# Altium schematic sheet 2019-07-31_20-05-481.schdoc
size 518 x 147 mm; SheetNumber: 1; SheetTotal: 1
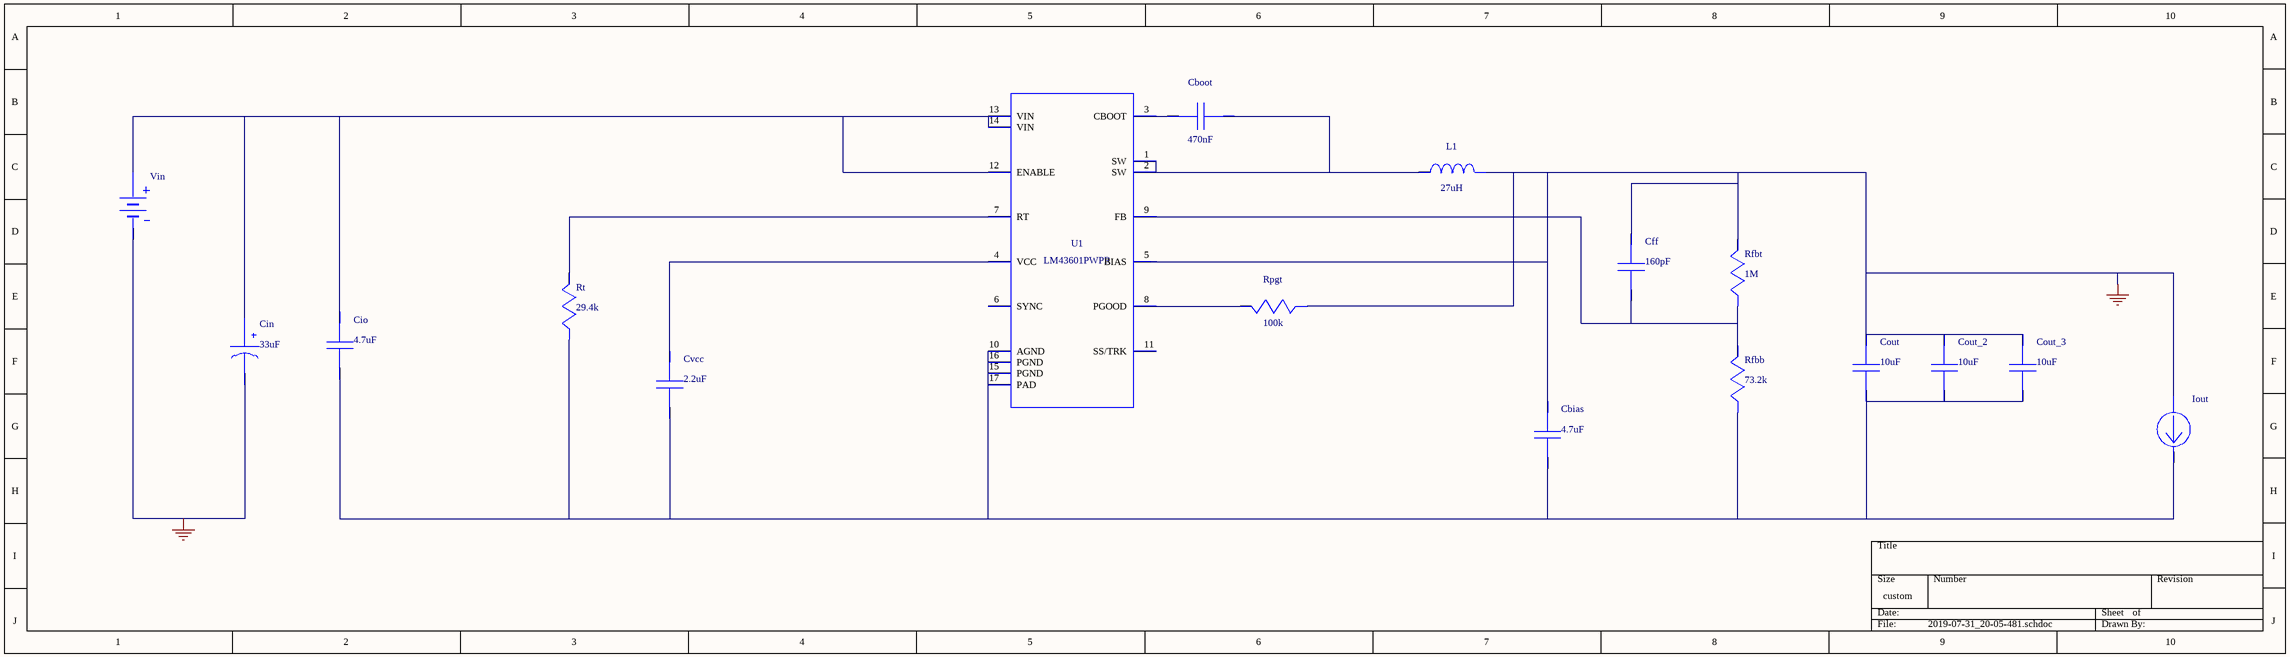
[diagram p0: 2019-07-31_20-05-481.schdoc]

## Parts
Cbias  value 4.7uF  (hidden comment: TMK212BJ475KG-T)
Cboot  value 470nF  (hidden comment: GRM155R60J474KE19D)
Cff  value 160pF  (hidden comment: GRM1555C1H161JA01D)
Cin  value 33uF  (hidden comment: EEE-FK1A330UR)
Cio  value 4.7uF  (hidden comment: C1608X5R1V475K080AC)
Cout  value 10uF  (hidden comment: CL32B106KBJNNWE)
Cout_2  value 10uF  (hidden comment: CL32B106KBJNNWE)
Cout_3  value 10uF  (hidden comment: CL32B106KBJNNWE)
Cvcc  value 2.2uF  (hidden comment: EMK212BJ225KG-T)
Iout  WB_CURRENT_LOAD  (value not drawn)
L1  value 27uH  (hidden comment: ME3220-273KLB)
Rfbb  value 73.2k  (hidden comment: CRCW040273K2FKED)
Rfbt  value 1M  (hidden comment: CRCW04021M00FKED)
Rpgt  value 100k  (hidden comment: CRCW0402100KFKED)
Rt  value 29.4k  (hidden comment: CRCW040229K4FKED)
U1  LM43603PWPR  (value not drawn)
Vin  WB_BATTERY  (value not drawn)

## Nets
0: Cbias.1 Cff.1 Cin.2(-) Cout.1 Cout_2.1 Cout_3.1 Iout.1(+) L1.2 Rfbt.1 Rpgt.2 U1.5(BIAS) Vin.2(-)
NetCbias_2: Cbias.2 Cio.2 Cout.2 Cout_2.2 Cout_3.2 Cvcc.2 Iout.2(-) Rfbb.2 Rt.2 U1.10(AGND) U1.15(PGND) U1.16(PGND) U1.17(PAD)
NetCboot_1: Cboot.1 L1.1 U1.1(SW) U1.2(SW)
NetCboot_2: Cboot.2 U1.3(CBOOT)
NetCff_2: Cff.2 Rfbb.1 Rfbt.2 U1.9(FB)
NetCin_1: Cin.1(+) Cio.1 U1.12(ENABLE) U1.13(VIN) U1.14(VIN) Vin.1(+)
NetCvcc_1: Cvcc.1 U1.4(VCC)
NetRpgt_1: Rpgt.1 U1.8(PGOOD)
NetRt_1: Rt.1 U1.7(RT)

Not connected (* = marked no-connect by the designer): U1 6(SYNC) 11(SS/TRK)

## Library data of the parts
Cbias = TMK212BJ475KG-T: Manufacturer Name: Taiyo Yuden
Cboot = GRM155R60J474KE19D: GRM155R60J474KE1; Manufacturer Name: MuRata
Cff = GRM1555C1H161JA01D: GRM1555C1H161JA0; Manufacturer Name: MuRata
Cin = EEE-FK1A330UR: Manufacturer Name: Panasonic
Cio = C1608X5R1V475K080AC: C1608X5R1V475K08; Manufacturer Name: TDK
Cout Cout_2 Cout_3 = CL32B106KBJNNWE: Manufacturer Name: Samsung Electro-Mechanics
Cvcc = EMK212BJ225KG-T: Manufacturer Name: Taiyo Yuden
L1 = ME3220-273KLB: Manufacturer Name: Coilcraft
Rfbb = CRCW040273K2FKED: Manufacturer Name: Vishay-Dale
Rfbt = CRCW04021M00FKED: Manufacturer Name: Vishay-Dale
Rpgt = CRCW0402100KFKED: Manufacturer Name: Vishay-Dale
Rt = CRCW040229K4FKED: Manufacturer Name: Vishay-Dale
U1 = LM43603PWPR: LM43601PWPR; Manufacturer Name: Texas Instruments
